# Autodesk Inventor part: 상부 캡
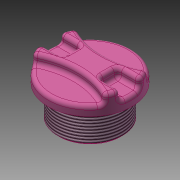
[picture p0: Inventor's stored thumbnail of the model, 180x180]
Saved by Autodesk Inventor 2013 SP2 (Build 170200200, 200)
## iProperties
Created: 2016-09
Part Number: 상부 캡
Material: ABS 플라스틱
Document SubType Name: Modeling
Designer: mduedu
Density: 1.06 g/cm^3
Author: mduedu
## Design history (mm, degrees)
sketch "스케치1"
  geometry: C1 r 22.5 at (0, 0); 1 further point
  constraints: 1 centre point, 1 coincident
  dimensions: "d0" = 45 diameter of C1
extrude "돌출1" new body sketch "스케치1" distance "d1" = 10; taper "d2" = 0 deg
sketch "스케치2" dims "d4" = 80
  geometry: C1 r 22.5 at (0, 0) reference; 3 further points
  constraints: 3 vertical alignment, 2 other
  dimensions: "d3" = 7 distance of point (0, 7) point (0, 0)
extrude "돌출2" cut sketch "스케치2" distance "d5" = 5; taper "d6" = 0 deg
sketch "스케치3"
  geometry: L1 (-22.5, 0)-(0, 0); L2 (-21.937, 5)-(-10, 5); L3 (-10, 5)-(-10, -5); L4 (-10, -5)-(-21.937, -5); A1 r 22.5 centre (0, 0) between (-19.118, 11.864) and (-19.118, -11.864) reference; A2 r 22.5 centre (0, 0) between (-21.937, 5) and (-21.937, -5); 1 further point
  constraints: 8 end point, 5 point on circle, 2 horizontal, 1 centre point, 1 coincident, 1 parallel, 1 perpendicular, 1 symmetric about line
  dimensions: "d7" = 10 distance from line of L3 point (0, 0); "d8" = 10 distance of L2.end L3.end
extrude "돌출3" cut sketch "스케치3" distance "d9" = 5; taper "d10" = 0 deg
fillet "모깎기1" dims "d11" = 2
fillet "모깎기2" dims "d12" = 2
fillet "모깎기3" dims "d13" = 2
sketch "스케치4"
  geometry: C1 r 17.5 at (0, 0); 1 further point
  constraints: 1 centre point, 1 coincident
  dimensions: "d14" = 35 diameter of C1
extrude "돌출4" join sketch "스케치4" distance "d15" = 17; taper "d16" = 0 deg
sketch "스케치5"
  geometry: C1 r 12.5 at (0, 0); 1 further point
  constraints: 1 centre point, 1 coincident
  dimensions: "d17" = 25 diameter of C1
extrude "돌출5" cut sketch "스케치5" distance "d18" = 10; taper "d19" = 0 deg
fillet "모깎기4" dims "d20" = 3
feature "스레드1" dims "d21" = 10, "d22" = 0
chamfer "모따기1" distance "d23" = 1; stored, may be unused: second distance "d24" = 2, angle "d25" = 45 deg
node "솔리드1"
mirror "대칭1"
mirror "대칭2"
node "투영된 루프1"
